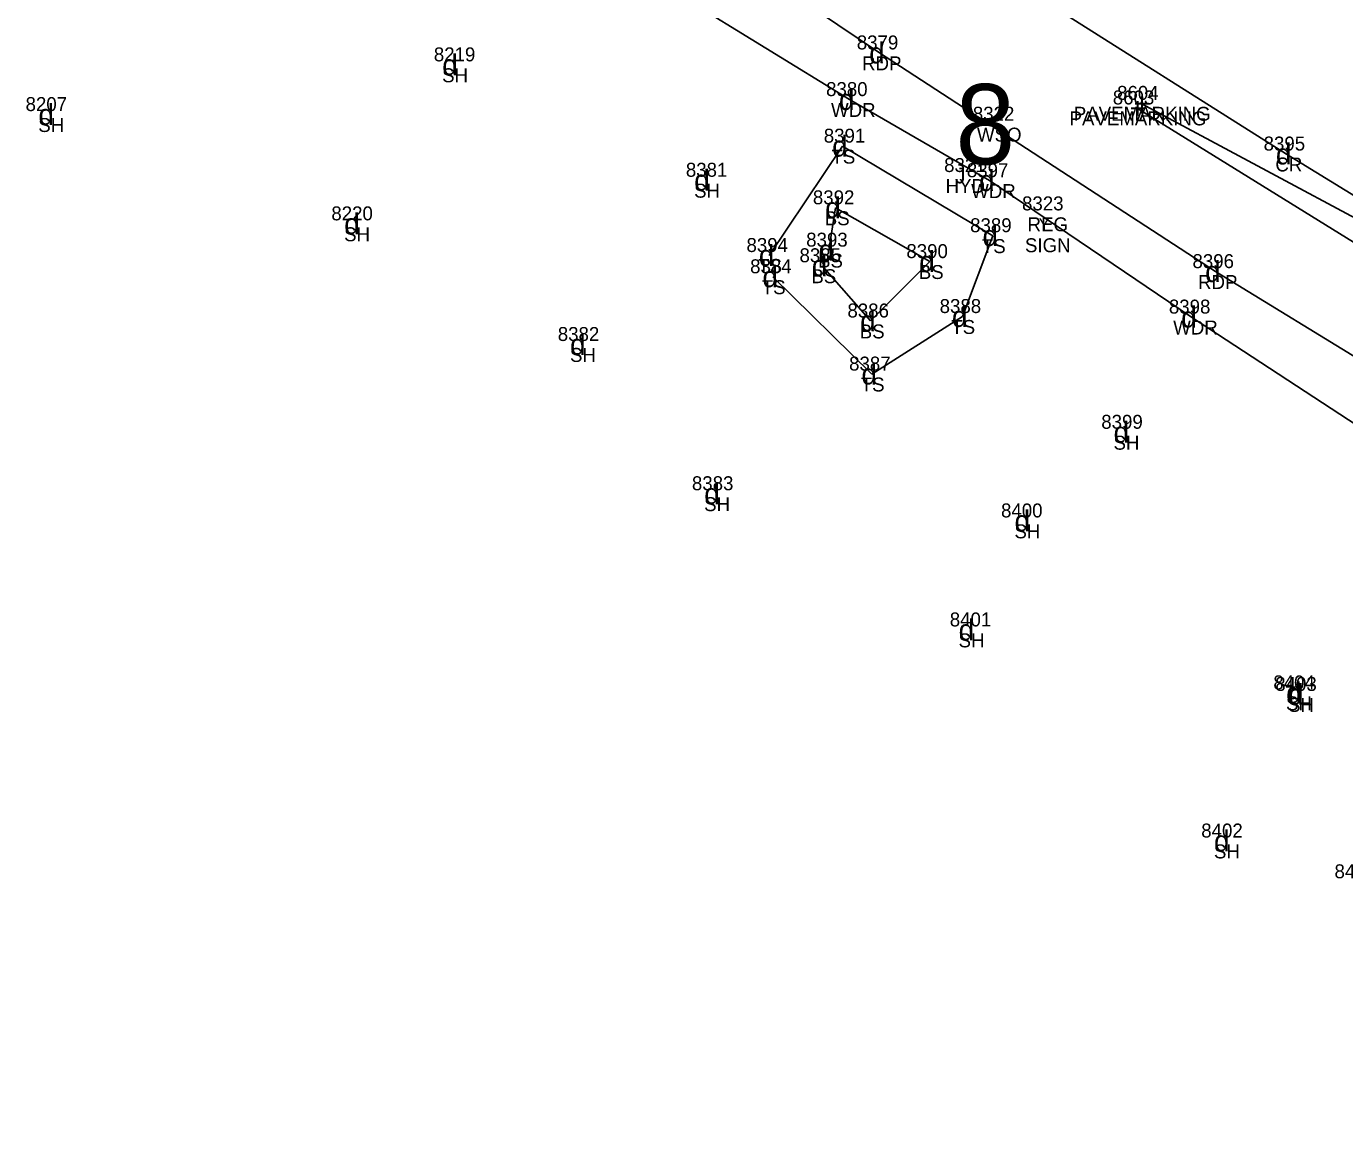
# Model space of a CAD drawing. Extents: x 69415 to 80913, y 7576 to 15059.
# Drawn here: x 77237.5 to 77426.5, y 13221.7 to 13381.5 of the extents above; entities that cross this region are included whole.
import ezdxf

# ---------------------------------------------------------------- set-up
doc = ezdxf.new("R2010")
doc.units = 0
for name, color, linetype in [('Level 11', 7, 'Continuous'), ('Level 14', 7, 'Continuous'), ('Level 15', 7, 'Continuous'), ('Level 43', 7, 'Continuous'), ('Level 45', 7, 'Continuous'), ('Level 46', 7, 'Continuous'), ('Level 47', 7, 'Continuous'), ('Level 48', 7, 'Continuous')]:
    doc.layers.add(name, color=color, linetype=linetype)

msp = doc.modelspace()

# ---------------------------------------------------------------- linework, layer by layer
at = {"layer": 'Level 11'}
for p, q in [((77319.5, 13404.9), (77359.83, 13377.72)), ((77359.83, 13377.72), (77407.99, 13346.36)), ((77407.99, 13346.36), (77450.92, 13320.1))]:
    msp.add_line(p, q, dxfattribs=at)
at = {"layer": 'Level 14'}
for p, q in [((77312.77, 13397.33), (77355.5, 13371.03)), ((77355.5, 13371.03), (77375.6, 13359.4)), ((77375.6, 13359.4), (77404.56, 13339.84)), ((77404.56, 13339.84), (77446.5, 13312.31))]:
    msp.add_line(p, q, dxfattribs=at)
at = {"layer": 'Level 45'}
for p, q in [((77635.78, 13221.74), (77396.64, 13369.83)), ((77397.25, 13370.49), (77546.4, 13290.63))]:
    msp.add_line(p, q, dxfattribs=at)
at = {"layer": 'Level 48'}
for p, q in [((77370.65, 13393.27), (77418.14, 13363.22)), ((77354.52, 13364.35), (77344.01, 13348.67)), ((77376.08, 13351.51), (77354.52, 13364.35)), ((77418.14, 13363.22), (77460.95, 13336.81)), ((77353.53, 13355.51), (77352.57, 13349.44)), ((77367.01, 13347.8), (77353.53, 13355.51)), ((77371.7, 13339.92), (77376.08, 13351.51)), ((77351.61, 13347.2), (77358.54, 13339.28)), ((77358.54, 13339.28), (77367.01, 13347.8)), ((77344.53, 13345.62), (77358.72, 13331.67)), ((77358.72, 13331.67), (77371.7, 13339.92))]:
    msp.add_line(p, q, dxfattribs=at)

# ---------------------------------------------------------------- texts
at = {"layer": 'Level 15'}
for s, height, p in [('8', 11.5, (77370.71, 13361.75)), ('J', 2.26, (77370.64, 13359.01))]:
    msp.add_text(s, height=height, dxfattribs=at).set_placement(p)
at = {"layer": 'Level 43'}
msp.add_text('Y', height=1.7, dxfattribs=at).set_placement((77382.66, 13352.29))
at = {"layer": 'Level 46'}
for s, p in [('8379', (77356.56, 13378.22)), ('8219', (77295.93, 13376.51)), ('RDP', (77357.32, 13375.22)), ('SH', (77297.12, 13373.51)), ('8380', (77352.16, 13371.53)), ('8603', (77393.26, 13370.33)), ('8604', (77393.87, 13370.99)), ('8207', (77237.41, 13369.38)), ('WDR', (77352.87, 13368.53)), ('8322', (77373.2, 13368)), ('PAVEMARKING', (77387.67, 13367.99)), ('SH', (77239.23, 13366.38)), ('PAVEMARKING', (77387.06, 13367.33)), ('8391', (77351.83, 13364.85)), ('WSO', (77373.79, 13365)), ('8395', (77414.88, 13363.72)), ('TS', (77352.93, 13361.85)), ('8321', (77369.08, 13360.64)), ('CR', (77416.57, 13360.72)), ('8381', (77332.06, 13359.96)), ('8397', (77372.34, 13359.9)), ('SH', (77333.24, 13356.96)), ('HYD', (77369.29, 13357.64)), ('WDR', (77372.96, 13356.9)), ('8392', (77350.27, 13356.01)), ('8323', (77380.25, 13355.14)), ('8220', (77281.24, 13353.71)), ('BS', (77351.97, 13353.01)), ('SH', (77283.07, 13350.71)), ('8389', (77372.81, 13352.01)), ('REG', (77381.04, 13352.14)), ('8394', (77340.75, 13349.17)), ('8393', (77349.31, 13349.94)), ('TS', (77374.49, 13349.01)), ('SIGN', (77380.67, 13349.14)), ('8385', (77348.35, 13347.7)), ('BS', (77351.01, 13346.94)), ('8390', (77363.67, 13348.3)), ('8396', (77404.68, 13346.86)), ('8384', (77341.27, 13346.12)), ('TS', (77342.42, 13346.17)), ('BS', (77365.45, 13345.3)), ('TS', (77342.94, 13343.12)), ('BS', (77350.05, 13344.7)), ('RDP', (77405.48, 13343.86)), ('8386', (77355.22, 13339.78)), ('8388', (77368.44, 13340.42)), ('8398', (77401.3, 13340.34)), ('TS', (77370.11, 13337.42)), ('8382', (77313.7, 13336.41)), ('BS', (77356.98, 13336.78)), ('WDR', (77401.92, 13337.34)), ('SH', (77315.45, 13333.41)), ('8387', (77355.46, 13332.17)), ('TS', (77357.13, 13329.17)), ('8399', (77391.61, 13323.82)), ('SH', (77393.36, 13320.82)), ('8383', (77332.93, 13315.01)), ('SH', (77334.68, 13312.01)), ('8400', (77377.24, 13311.11)), ('SH', (77379.16, 13308.11)), ('8401', (77369.89, 13295.48)), ('SH', (77371.15, 13292.48)), ('8404', (77416.27, 13286.45)), ('8403', (77416.55, 13286.23)), ('SH', (77418.09, 13283.45)), ('SH', (77418.38, 13283.23)), ('8402', (77405.94, 13265.21)), ('SH', (77407.76, 13262.21)), ('8407', (77425.04, 13259.36))]:
    msp.add_text(s, height=2, dxfattribs=at).set_placement(p)
at = {"layer": 'Level 47'}
for s, p in [('d', (77358.33, 13376.22)), ('d', (77297.13, 13374.51)), ('d', (77354, 13369.53)), ('d', (77239.25, 13367.38)), ('+', (77395.66, 13368.33)), ('+', (77396.27, 13368.99)), ('d', (77353.02, 13362.85)), ('d', (77416.64, 13361.72)), ('d', (77333.25, 13357.96)), ('d', (77374.1, 13357.9)), ('d', (77352.03, 13354.01)), ('d', (77283.08, 13351.71)), ('d', (77374.58, 13350.01)), ('d', (77351.07, 13347.94)), ('d', (77342.51, 13347.17)), ('d', (77365.51, 13346.3)), ('d', (77343.03, 13344.12)), ('d', (77350.11, 13345.7)), ('d', (77406.49, 13344.86)), ('d', (77370.2, 13338.42)), ('d', (77403.06, 13338.34)), ('d', (77357.04, 13337.78)), ('d', (77315.46, 13334.41)), ('d', (77357.22, 13330.17)), ('d', (77393.37, 13321.82)), ('d', (77334.69, 13313.01)), ('d', (77379.17, 13309.11)), ('d', (77371.16, 13293.48)), ('d', (77418.11, 13284.45)), ('d', (77418.39, 13284.23)), ('d', (77407.77, 13263.21))]:
    msp.add_text(s, height=3, dxfattribs=at).set_placement(p)

doc.saveas('drawing.dxf')
